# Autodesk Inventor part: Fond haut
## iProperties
Author: Flavien MARTY
Shininess: 20.0
PropertySet Name: _Private Model Information
Created: 2001-10
Part Number: Fond haut
Material: Par défaut
Document SubType Name: Modélisation
Designer: Flavien MARTY
Control State: 0
Master: False
Checked Out: False
PropertySet Name: Design Tracking Control
Density: 0.0
Volumn: 0.0
Area: 0.0
PropertySet Name: Model Information
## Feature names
1. Base1
